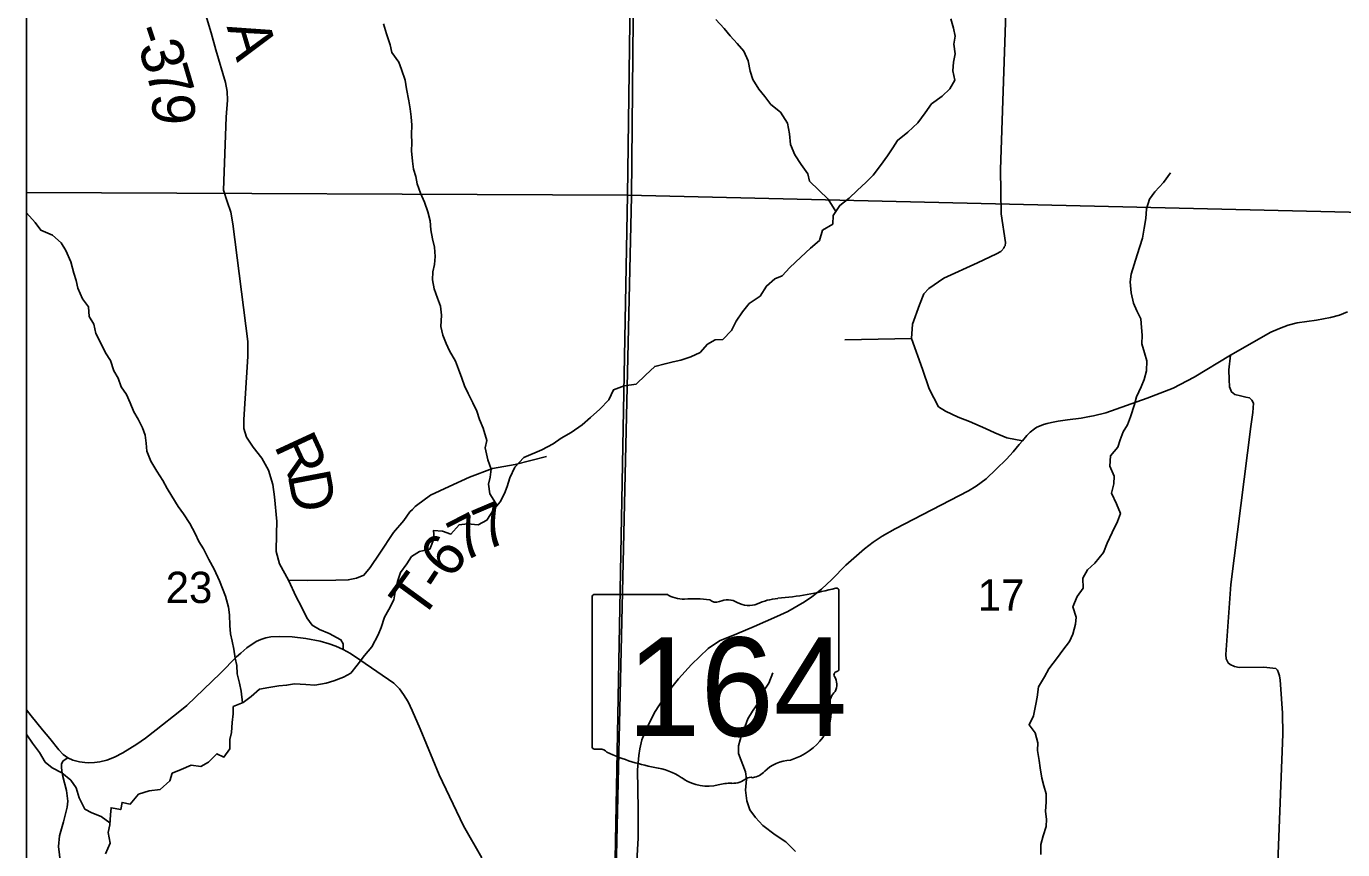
# Model space of a CAD drawing. Extents: x -3.6 to 34, y 0 to 32.8.
# Drawn here: x -3.63 to -1.871, y 27.186 to 28.286 of the extents above; entities that cross this region are included whole.
import ezdxf

# ---------------------------------------------------------------- set-up
doc = ezdxf.new("R2010")
doc.units = 0
for name, color, linetype in [('GM_X_Corporation', 7, 'Continuous'), ('GM_X_Minor_River', 7, 'Continuous'), ('GM_X_Section_Text', 7, 'Continuous'), ('GM_X_State_Location', 7, 'Continuous'), ('GM_X_State_Route', 7, 'Continuous'), ('GM_X_State_Shield', 7, 'Continuous'), ('GM_X_Township_Road', 7, 'Continuous'), ('GM_X_Township_Road_Text', 7, 'Continuous'), ('SH_Data', 7, 'Continuous')]:
    doc.layers.add(name, color=color, linetype=linetype)

msp = doc.modelspace()

# ---------------------------------------------------------------- linework, layer by layer
at = {"layer": 'GM_X_Corporation'}
for points in [[(3.1705, 28.9337), (3.1705, 32.8429), (-3.6295, 32.8429), (-3.6295, 26.0429), (2.3706, 26.0429), (2.3712, 26.0804), (2.3716, 26.1248), (2.3732, 26.2253), (2.3789, 26.6097), (2.3911, 27.5117), (2.3952, 27.9336), (2.3997, 28.282), (2.4082, 28.9473), (2.5416, 28.945), (2.5837, 28.9442), (2.8343, 28.9397)], [(-3.6295, 30.6462), (-3.6295, 26.0429), (-2.8635, 26.0429), (-2.8499, 26.4099), (-2.8426, 27.1), (-2.8208, 28.0589), (-2.813, 28.9119), (-2.8073, 29.6484), (-2.8047, 30.129), (-2.8012, 30.524), (-2.8007, 30.6338), (-3.5736, 30.6453)], [(-3.6295, 29.124), (-3.6295, 28.0641), (-2.8264, 28.0607), (-2.8121, 29.1143)], [(-2.8121, 29.1143), (-1.8059, 29.1018), (-1.7854, 29.1006), (-1.8056, 28.0368), (-2.8264, 28.0607)], [(-3.6295, 28.0641), (-3.6295, 27.0475), (-2.8456, 27.0298), (-2.8264, 28.0607)], [(-1.8056, 28.0368), (-1.8251, 27.0226), (-2.8456, 27.0298), (-2.8264, 28.0607)]]:
    msp.add_lwpolyline(points, close=True, dxfattribs=at)
msp.add_lwpolyline([(-0.398, 30.5946), (-0.453, 30.5952), (-0.5034, 30.5954), (-2.3541, 30.6318), (-2.7027, 30.634), (-2.8007, 30.6338), (-2.8012, 30.524), (-2.8047, 30.129), (-2.8073, 29.6484), (-2.813, 28.9119), (-2.8208, 28.0589), (-2.8426, 27.1), (-2.8499, 26.4099), (-2.8635, 26.0429), (2.3706, 26.0429)], dxfattribs=at)
at = {"layer": 'GM_X_Minor_River'}
for points in [[(-3.0002, 27.646), (-3.01, 27.6616), (-3.0121, 27.6745), (-3.0096, 27.684), (-3.0083, 27.6946), (-3.0127, 27.7071), (-3.0164, 27.7233), (-3.0142, 27.7328), (-3.0191, 27.7494), (-3.0238, 27.7611), (-3.0278, 27.772), (-3.0329, 27.7833), (-3.0392, 27.7957), (-3.0439, 27.8059), (-3.0478, 27.8161), (-3.0522, 27.8281), (-3.0562, 27.8391), (-3.064, 27.8526), (-3.0687, 27.8624), (-3.073, 27.8737), (-3.0755, 27.8854), (-3.075, 27.9002), (-3.0763, 27.9123), (-3.0803, 27.9232), (-3.0847, 27.9353), (-3.0868, 27.9474), (-3.0862, 27.9584), (-3.0841, 27.9679), (-3.0832, 27.9785), (-3.0841, 27.9914), (-3.0866, 28.0023), (-3.0891, 28.0144), (-3.09, 28.0262), (-3.0929, 28.0386), (-3.0976, 28.0511), (-3.1028, 28.0635), (-3.1071, 28.0756), (-3.1092, 28.0854), (-3.112, 28.0956), (-3.1137, 28.1062), (-3.1147, 28.1198), (-3.1145, 28.1304), (-3.1147, 28.1418), (-3.1145, 28.1543), (-3.1155, 28.1653), (-3.1168, 28.1759), (-3.1185, 28.1865), (-3.1214, 28.2027), (-3.1235, 28.2144), (-3.1283, 28.2287), (-3.1319, 28.2385), (-3.1412, 28.2513), (-3.1432, 28.2615), (-3.1484, 28.2762), (-3.1524, 28.2894)], [(-2.9835, 27.6829), (-2.9769, 27.6974), (-2.965, 27.7102), (-2.9406, 27.7204), (-2.9256, 27.7283), (-2.9147, 27.7361), (-2.9016, 27.7435), (-2.8867, 27.754), (-2.8755, 27.7636), (-2.8632, 27.7749), (-2.8513, 27.7872), (-2.845, 27.8006), (-2.8308, 27.8061), (-2.8149, 27.8083), (-2.8022, 27.8203), (-2.7899, 27.8319), (-2.776, 27.8355), (-2.7654, 27.838), (-2.7552, 27.8404), (-2.7417, 27.8448), (-2.7293, 27.8503), (-2.7193, 27.8615), (-2.7091, 27.8674), (-2.6989, 27.8679), (-2.6874, 27.8799), (-2.6812, 27.8925), (-2.6727, 27.9048), (-2.6638, 27.9159), (-2.6492, 27.9257), (-2.6407, 27.9391), (-2.6295, 27.9491), (-2.6197, 27.9527), (-2.6093, 27.9639), (-2.5948, 27.9778), (-2.5818, 27.9898), (-2.5698, 28.0002), (-2.5655, 28.0139), (-2.552, 28.0221), (-2.5515, 28.0335), (-2.5426, 28.0469), (-2.5303, 28.0566), (-2.5195, 28.0667), (-2.5075, 28.0779), (-2.4979, 28.0875), (-2.4882, 28.1002), (-2.479, 28.1132), (-2.4716, 28.124), (-2.4654, 28.1339), (-2.4515, 28.1448), (-2.4385, 28.1575), (-2.4285, 28.1706), (-2.42, 28.1825), (-2.4058, 28.193), (-2.3957, 28.2026), (-2.3887, 28.2141), (-2.3916, 28.2269), (-2.3907, 28.2383), (-2.3886, 28.2494), (-2.3903, 28.2626), (-2.3886, 28.2732), (-2.3907, 28.2838), (-2.3943, 28.2963)], [(-2.5479, 28.0389), (-2.5583, 28.0554), (-2.5829, 28.0792), (-2.5853, 28.089), (-2.5943, 28.1018), (-2.6028, 28.1145), (-2.6084, 28.1284), (-2.6097, 28.1425), (-2.6126, 28.1568), (-2.622, 28.1714), (-2.6346, 28.1818), (-2.6428, 28.1923), (-2.6509, 28.2024), (-2.659, 28.2152), (-2.6623, 28.2265), (-2.6651, 28.2401), (-2.6707, 28.2529), (-2.6799, 28.2633), (-2.6892, 28.2734), (-2.6973, 28.2835), (-2.7081, 28.2955)], [(-2.2634, 27.4279), (-2.2515, 27.4429), (-2.2448, 27.4528), (-2.2356, 27.4644), (-2.2312, 27.4743), (-2.2276, 27.4873), (-2.2267, 27.4968), (-2.2314, 27.5107), (-2.2256, 27.5245), (-2.2175, 27.5356), (-2.2177, 27.5489), (-2.2118, 27.56), (-2.2018, 27.5689), (-2.1903, 27.5831), (-2.1852, 27.5957), (-2.1786, 27.6099), (-2.1717, 27.6248), (-2.1677, 27.6355), (-2.1728, 27.6483), (-2.1795, 27.6626), (-2.1763, 27.6751), (-2.1761, 27.6854), (-2.182, 27.6986), (-2.1807, 27.7122), (-2.1711, 27.7238), (-2.1678, 27.7337), (-2.1638, 27.7444), (-2.1583, 27.7539), (-2.1543, 27.7646), (-2.1489, 27.781), (-2.1461, 27.7913), (-2.1399, 27.8047), (-2.1359, 27.8143), (-2.133, 27.8261), (-2.1325, 27.8393), (-2.1353, 27.8499), (-2.139, 27.862), (-2.1388, 27.8734), (-2.1393, 27.884), (-2.1403, 27.8953), (-2.1458, 27.9062), (-2.1501, 27.9164), (-2.1534, 27.9304), (-2.1547, 27.9448), (-2.1534, 27.955), (-2.1495, 27.968), (-2.1451, 27.9809), (-2.1415, 27.992), (-2.1383, 28.0034), (-2.1359, 28.0164), (-2.1338, 28.0293), (-2.1329, 28.0426), (-2.1286, 28.0555), (-2.1216, 28.0651), (-2.1101, 28.0778), (-2.1008, 28.0905)], [(-3.3408, 27.3825), (-3.3425, 27.398), (-3.3446, 27.4086), (-3.3478, 27.4211), (-3.3484, 27.4321), (-3.3504, 27.4419), (-3.3521, 27.454), (-3.3546, 27.4646), (-3.3566, 27.4744), (-3.3576, 27.4858), (-3.3582, 27.4998), (-3.3595, 27.51), (-3.3635, 27.5247), (-3.3675, 27.5353), (-3.3715, 27.5455), (-3.3785, 27.5609), (-3.3856, 27.5737), (-3.3926, 27.5883), (-3.3992, 27.5981), (-3.404, 27.6086), (-3.411, 27.6218), (-3.4195, 27.6349), (-3.4265, 27.6446), (-3.4351, 27.6585), (-3.4413, 27.6687), (-3.4472, 27.6796), (-3.455, 27.6919), (-3.4631, 27.7051), (-3.4687, 27.7186), (-3.4696, 27.7292), (-3.4709, 27.7398), (-3.4741, 27.75), (-3.48, 27.7613), (-3.4858, 27.7714), (-3.4909, 27.7831), (-3.4957, 27.7944), (-3.503, 27.8045), (-3.5067, 27.8162), (-3.5125, 27.826), (-3.5169, 27.8399), (-3.5239, 27.85), (-3.5286, 27.8602), (-3.5368, 27.876), (-3.5393, 27.8881), (-3.5455, 27.8986), (-3.5465, 27.9115), (-3.5543, 27.922), (-3.5609, 27.9363), (-3.563, 27.9465), (-3.5662, 27.9563), (-3.5699, 27.9714), (-3.5769, 27.9868), (-3.5832, 27.9969), (-3.5947, 28.0073), (-3.6103, 28.0139), (-3.6177, 28.024), (-3.6293, 28.0371), (-3.6295, 28.0374)], [(-3.5239, 27.1806), (-3.5177, 27.1948), (-3.5202, 27.2091), (-3.5181, 27.2194), (-3.5169, 27.2327), (-3.5163, 27.2422), (-3.5034, 27.2398), (-3.5016, 27.2493), (-3.4906, 27.2472), (-3.4795, 27.2603), (-3.4655, 27.2647), (-3.4508, 27.2665), (-3.4378, 27.2784), (-3.4345, 27.2884), (-3.4225, 27.2935), (-3.4093, 27.299), (-3.3964, 27.2974), (-3.3859, 27.3032), (-3.3751, 27.3144), (-3.3656, 27.31), (-3.3578, 27.3208), (-3.3577, 27.3333), (-3.3552, 27.3428), (-3.3543, 27.3561), (-3.3533, 27.3679), (-3.3531, 27.3774), (-3.34, 27.3829), (-3.3291, 27.391), (-3.3179, 27.4007), (-3.3055, 27.4028), (-3.2923, 27.405), (-3.2817, 27.4059), (-3.2711, 27.408), (-3.2559, 27.4067), (-3.2442, 27.4061), (-3.2291, 27.4087), (-3.2186, 27.4119), (-3.2058, 27.4167), (-3.196, 27.4221), (-3.1875, 27.4325), (-3.1779, 27.4456), (-3.1678, 27.4571), (-3.1594, 27.4732), (-3.1554, 27.4831), (-3.1511, 27.4969), (-3.1452, 27.5072), (-3.1386, 27.5202), (-3.1365, 27.5309), (-3.1337, 27.5446), (-3.1294, 27.5564), (-3.1209, 27.5683), (-3.115, 27.5779), (-3.1041, 27.5845), (-3.0902, 27.5878), (-3.0847, 27.6023), (-3.0857, 27.6125), (-3.0735, 27.6116), (-3.0621, 27.6076), (-3.0513, 27.6203), (-3.04, 27.6217), (-3.0256, 27.6204), (-3.014, 27.6266), (-3.0051, 27.6401), (-2.9962, 27.6508), (-2.9907, 27.6619), (-2.9871, 27.6715), (-2.9835, 27.6829)], [(-2.6019, 27.1838), (-2.6146, 27.1969), (-2.6291, 27.2061), (-2.6456, 27.2184), (-2.6552, 27.2292), (-2.663, 27.2393), (-2.667, 27.2514), (-2.6687, 27.2658), (-2.6674, 27.2802), (-2.6684, 27.29), (-2.6779, 27.3149), (-2.678, 27.3248), (-2.6734, 27.3412), (-2.669, 27.3511), (-2.6654, 27.361), (-2.6591, 27.3714), (-2.6503, 27.3844), (-2.6444, 27.3978), (-2.6374, 27.4085), (-2.6323, 27.4223)], [(-2.274, 27.1796), (-2.2742, 27.1932), (-2.271, 27.2047), (-2.267, 27.2172), (-2.2664, 27.2271), (-2.2677, 27.237), (-2.2668, 27.2503), (-2.267, 27.2609), (-2.2702, 27.2714), (-2.2726, 27.2816), (-2.2751, 27.2956), (-2.2764, 27.3055), (-2.2786, 27.3187), (-2.278, 27.329), (-2.2816, 27.3422), (-2.2897, 27.3531), (-2.2839, 27.3649), (-2.2807, 27.3805), (-2.279, 27.39), (-2.2773, 27.4037), (-2.2689, 27.4171), (-2.2634, 27.4279)], [(-3.5179, 27.2221), (-3.5297, 27.2306), (-3.5419, 27.2353), (-3.5514, 27.2405), (-3.5589, 27.2555), (-3.5629, 27.2687), (-3.5699, 27.2789), (-3.5822, 27.2889), (-3.5948, 27.2955), (-3.6044, 27.3033), (-3.6121, 27.3161), (-3.6214, 27.3284), (-3.6288, 27.3397), (-3.6295, 27.3407)]]:
    msp.add_lwpolyline(points, dxfattribs=at)
at = {"layer": 'GM_X_State_Route'}
for points in [[(-2.8139, 27.1708), (-2.8121, 27.2014), (-2.8118, 27.2404), (-2.8127, 27.2928), (-2.8113, 27.3121), (-2.8099, 27.3211), (-2.8069, 27.3329), (-2.8009, 27.3479), (-2.7891, 27.3709), (-2.7737, 27.3948), (-2.7583, 27.4144), (-2.7407, 27.4334), (-2.7184, 27.4552), (-2.7032, 27.4653), (-2.6802, 27.4748), (-2.657, 27.4844), (-2.6268, 27.4976), (-2.6122, 27.5044), (-2.5898, 27.5173), (-2.5798, 27.5242), (-2.5671, 27.5344), (-2.5534, 27.5472), (-2.5344, 27.5663), (-2.5097, 27.5883), (-2.4978, 27.5971), (-2.4859, 27.6049), (-2.4688, 27.6148), (-2.3705, 27.6657), (-2.3605, 27.6718), (-2.3471, 27.6817), (-2.3337, 27.6944), (-2.3198, 27.7079), (-2.3111, 27.7178), (-2.3029, 27.7275), (-2.2987, 27.7326), (-2.2926, 27.7397), (-2.2881, 27.744), (-2.2825, 27.7484), (-2.2792, 27.7505), (-2.2759, 27.7521), (-2.2705, 27.7542), (-2.2657, 27.7556), (-2.2596, 27.757), (-2.2509, 27.7586), (-2.2385, 27.7606), (-2.2203, 27.7629), (-2.2089, 27.7648), (-2.2035, 27.7659), (-2.1873, 27.77), (-2.1319, 27.7894), (-2.0972, 27.8029), (-2.069, 27.8176), (-2.0206, 27.8467), (-1.9666, 27.8775), (-1.955, 27.8826), (-1.9437, 27.887), (-1.9317, 27.8901), (-1.9058, 27.8935), (-1.8868, 27.8973), (-1.875, 27.9004), (-1.8641, 27.9046)], [(-3.6295, 27.3731), (-3.6229, 27.3649), (-3.6079, 27.3464), (-3.5981, 27.3346), (-3.5859, 27.3194), (-3.5801, 27.3135), (-3.5739, 27.3089), (-3.5675, 27.3058), (-3.5587, 27.3036), (-3.5513, 27.3026), (-3.5465, 27.3024), (-3.5385, 27.3026), (-3.5314, 27.3034), (-3.522, 27.3059), (-3.5116, 27.3099), (-3.5004, 27.3156), (-3.482, 27.3273), (-3.4701, 27.3353), (-3.456, 27.3463), (-3.4242, 27.3712), (-3.4152, 27.379), (-3.3703, 27.4222), (-3.3488, 27.4438), (-3.3431, 27.4489), (-3.3349, 27.4561), (-3.3223, 27.4643), (-3.3162, 27.4671), (-3.3097, 27.4694), (-3.3028, 27.4706), (-3.2916, 27.4712), (-3.2742, 27.4706), (-3.2562, 27.4682), (-3.2371, 27.4648), (-3.2251, 27.4614), (-3.2159, 27.4581), (-3.206, 27.4538), (-3.1964, 27.4481), (-3.184, 27.4398), (-3.1386, 27.4087), (-3.1311, 27.4011), (-3.1254, 27.3936), (-3.1194, 27.3839), (-3.1139, 27.3723), (-3.1034, 27.3475), (-3.0778, 27.2864), (-3.0456, 27.2179), (-3.0208, 27.1751)]]:
    msp.add_lwpolyline(points, dxfattribs=at)
at = {"layer": 'GM_X_State_Shield'}
for p, q in [((-2.7736, 27.5273), (-2.8702, 27.5273)), ((-2.5438, 27.4276), (-2.5438, 27.5323)), ((-2.8734, 27.5239), (-2.8734, 27.3238)), ((-2.5439, 27.4276), (-2.5438, 27.4276))]:
    msp.add_line(p, q, dxfattribs=at)
for centre, major_axis, start_param, end_param in [((-2.8696, 27.5243), (0.00382, 0), 1.712693, 3.28349), ((-2.7507, 27.5506), (0.037, 0), 4.042523, 4.731795), ((-2.6612, 27.8002), (0.3495, 0), 4.814394, 5.042369), ((-2.5475, 27.5327), (0.00367, 0), 6.141152, 7.989035), ((-2.7384, 27.415), (0.133, 0), 1.404758, 1.657858), ((-2.7082, 27.5254), (0.0107, 0), 3.836095, 5.185415), ((-2.6925, 27.5022), (0.0222, 0), 0.950623, 2.079405), ((-2.6638, 27.5339), (0.0267, 0), 4.081561, 5.145723), ((-2.6166, 27.4662), (0.0703, 0), 1.699011, 2.107814), ((-2.5447, 27.4199), (0.00568, 0), 1.883978, 3.671073), ((-2.5477, 27.4272), (0.00393, 0), 5.05454, 6.418171), ((-2.5808, 27.4067), (0.0341, 0), 5.934695, 6.695948), ((-2.5307, 27.3838), (0.0248, 0), 2.387724, 3.262537), ((-2.6416, 27.3705), (0.0874, 0), 5.101752, 6.440018), ((-2.8696, 27.3233), (0.00385, 0), 3.00124, 4.508301), ((-2.869, 27.3438), (0.0294, 0), 4.665946, 4.897461), ((-2.863, 27.3122), (0.0106, 0), 0.519207, 1.627899), ((-2.7292, 27.492), (0.2524, 0), 4.195997, 4.488961), ((-2.6048, 27.2676), (0.0479, 0), 1.647645, 2.488434), ((-2.8044, 27.2339), (0.079, 0), 0.823519, 1.323587), ((-2.719, 27.3112), (0.0501, 0), 4.026481, 4.996735), ((-2.6864, 27.2962), (0.0267, 0), 4.691044, 5.507374), ((-2.6622, 27.2769), (0.00752, 0), 1.147584, 2.315152), ((-2.6654, 27.3044), (0.0282, 0), 4.937069, 5.64225), ((-2.6901, 27.242), (0.0412, 0), 1.495662, 1.94098)]:
    msp.add_ellipse(centre, major_axis=major_axis, ratio=0.8, start_param=start_param, end_param=end_param, dxfattribs=at)
at = {"layer": 'GM_X_Township_Road'}
msp.add_line((-2.4468, 27.869), (-2.5358, 27.8675), dxfattribs=at)
for points in [[(-2.2987, 27.7326), (-2.3192, 27.7366), (-2.3354, 27.743), (-2.3478, 27.7491), (-2.3693, 27.7583), (-2.3844, 27.7642), (-2.4015, 27.7723), (-2.4109, 27.778), (-2.423, 27.8018), (-2.4319, 27.828), (-2.4468, 27.869), (-2.4455, 27.8881), (-2.436, 27.9142), (-2.4302, 27.9287), (-2.4238, 27.9359), (-2.4034, 27.9498), (-2.3585, 27.9702), (-2.3331, 27.9824), (-2.3274, 27.9852), (-2.3227, 27.9909), (-2.3237, 27.9909), (-2.3218, 27.9928), (-2.321, 27.9976), (-2.3271, 28.0358), (-2.3279, 28.0951), (-2.3155, 28.462)], [(-3.206, 27.4538), (-3.206, 27.4611), (-3.2093, 27.4667), (-3.2247, 27.4749), (-3.2379, 27.4802), (-3.2474, 27.4862), (-3.2548, 27.496), (-3.2625, 27.5114), (-3.2691, 27.5241), (-3.2792, 27.5463), (-3.2912, 27.5683), (-3.2956, 27.5848), (-3.2951, 27.608), (-3.295, 27.6248), (-3.2978, 27.6575), (-3.3002, 27.6743), (-3.3061, 27.6934), (-3.3149, 27.7092), (-3.3266, 27.724), (-3.3353, 27.7374), (-3.339, 27.7487), (-3.339, 27.7609), (-3.3335, 27.8451), (-3.3337, 27.865), (-3.3536, 28.0224), (-3.3562, 28.0379), (-3.3612, 28.0524), (-3.3659, 28.0673), (-3.3623, 28.1647), (-3.3607, 28.1877), (-3.3612, 28.1993), (-3.3634, 28.2113), (-3.3761, 28.2548), (-3.3826, 28.2777), (-3.3897, 28.3013)], [(-1.9572, 27.1691), (-1.9507, 27.3404), (-1.9512, 27.3685), (-1.9539, 27.4068), (-1.9543, 27.4128), (-1.9549, 27.4183), (-1.9565, 27.4226), (-1.9576, 27.4259), (-1.9602, 27.4283), (-1.9759, 27.4301), (-2.0092, 27.4298), (-2.0153, 27.4308), (-2.0208, 27.4336), (-2.0235, 27.4358), (-2.0262, 27.4412), (-2.0268, 27.4471), (-2.0199, 27.5405), (-1.9932, 27.7514), (-1.9907, 27.7702), (-1.99, 27.7828), (-1.9921, 27.7869), (-1.9953, 27.79), (-2.0001, 27.7909), (-2.0074, 27.7926), (-2.0146, 27.7945), (-2.0192, 27.7977), (-2.0219, 27.8045), (-2.0225, 27.8145), (-2.0227, 27.8274), (-2.0206, 27.8467)], [(-3.2792, 27.5463), (-3.2536, 27.5457), (-3.216, 27.5462), (-3.1995, 27.5467), (-3.1884, 27.5488), (-3.1784, 27.5531), (-3.1703, 27.5633), (-3.1572, 27.5825), (-3.139, 27.6101), (-3.1253, 27.6262), (-3.1171, 27.6374), (-3.1136, 27.6409), (-3.1101, 27.6445), (-3.1081, 27.6461), (-3.0894, 27.66), (-3.0647, 27.6716), (-3.0373, 27.6837), (-3.0068, 27.6957), (-2.9762, 27.7008), (-2.9344, 27.7115)], [(-3.6295, 27.0587), (-3.6118, 27.0796), (-3.5767, 27.1193), (-3.58, 27.1298), (-3.5822, 27.1366), (-3.583, 27.1606), (-3.5865, 27.1905), (-3.585, 27.2048), (-3.58, 27.2235), (-3.575, 27.2428), (-3.574, 27.2509), (-3.5759, 27.2652), (-3.5808, 27.2838), (-3.5822, 27.2913), (-3.5826, 27.2968), (-3.5826, 27.3011), (-3.5804, 27.3049), (-3.5739, 27.3089)]]:
    msp.add_lwpolyline(points, dxfattribs=at)
at = {"layer": 'SH_Data'}
msp.add_line((-3.6295, 32.8429), (-3.6295, 26.0429), dxfattribs=at)

# ---------------------------------------------------------------- texts
at = {"layer": 'GM_X_Section_Text'}
for s, p in [('23', (-3.4433, 27.5157)), ('17', (-2.3583, 27.5054))]:
    msp.add_text(s, height=0.04186, rotation=0, dxfattribs=at).set_placement(p)
at = {"layer": 'GM_X_State_Location'}
for s in ['s', 'r']:
    msp.add_text(s, height=0.000189, dxfattribs=at).set_placement((-2.7123, 27.4105))
msp.add_text('164', height=0.000189, rotation=0, dxfattribs=at).set_placement((-2.7792, 27.3967))
at = {"layer": 'GM_X_State_Shield'}
msp.add_text('164', height=0.13184, dxfattribs=at).set_placement((-2.8269, 27.3379))
at = {"layer": 'GM_X_Township_Road_Text'}
for s, rotation, p in [('-', 288.4831, (-3.4877, 28.2812)), ('A', 286.5489, (-3.3621, 28.2858)), ('3', 286.5652, (-3.4804, 28.2595)), ('7', 286.4515, (-3.4705, 28.226)), ('9', 270.0729, (-3.4612, 28.1967)), ('R', 294.8324, (-3.2991, 27.726)), ('D', 280.7841, (-3.2806, 27.6872)), ('7', 22.9786, (-3.0165, 27.585)), ('7', 27.3168, (-3.0466, 27.5694)), ('6', 52.07, (-3.0631, 27.5459)), ('T', 53.8998, (-3.102, 27.4908)), ('-', 56.4921, (-3.0754, 27.5274))]:
    msp.add_text(s, height=0.0568, rotation=rotation, dxfattribs=at).set_placement(p)

doc.saveas('drawing.dxf')
